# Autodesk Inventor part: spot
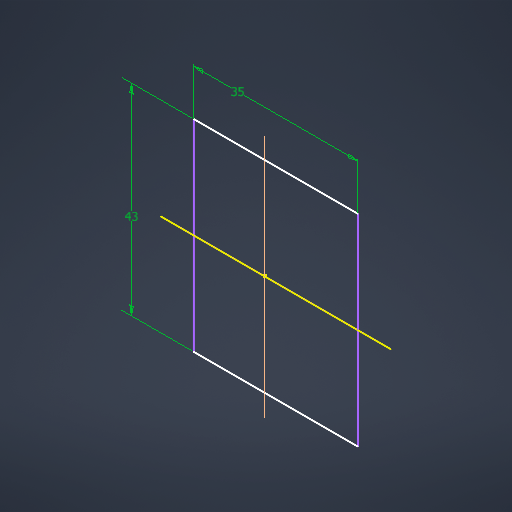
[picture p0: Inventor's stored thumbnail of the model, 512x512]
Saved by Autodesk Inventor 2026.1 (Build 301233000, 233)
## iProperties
Created: 2025-11
Part Number: spot
Material: Generico
Document SubType Name: Modeling
Designer: Gek
Density: 1 g/cm^3
Appearance: Default
Author: Gek
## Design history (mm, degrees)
sketch "Schizzo1"
  geometry: L1 (15.155, 21.5)-(-19.845, 21.5); L2 (-19.845, 21.5)-(-19.845, -21.5); L3 (-19.845, -21.5)-(15.155, -21.5); L4 (15.155, -21.5)-(15.155, 21.5); L5 (22.155, 0)-(-26.845, 0) reference; 1 further point
  constraints: 8 end point, 2 parallel, 1 horizontal, 1 perpendicular, 1 other
  dimensions: "d0" = 35 dimension on point (0, 0) L1.start L2.end L1.end L3.end L1 L2 L3 L4 L5.start L5.end L5; "d0" = 35 distance of L1.start L1.end; "d1" = 43 distance of L3.end L1.start
